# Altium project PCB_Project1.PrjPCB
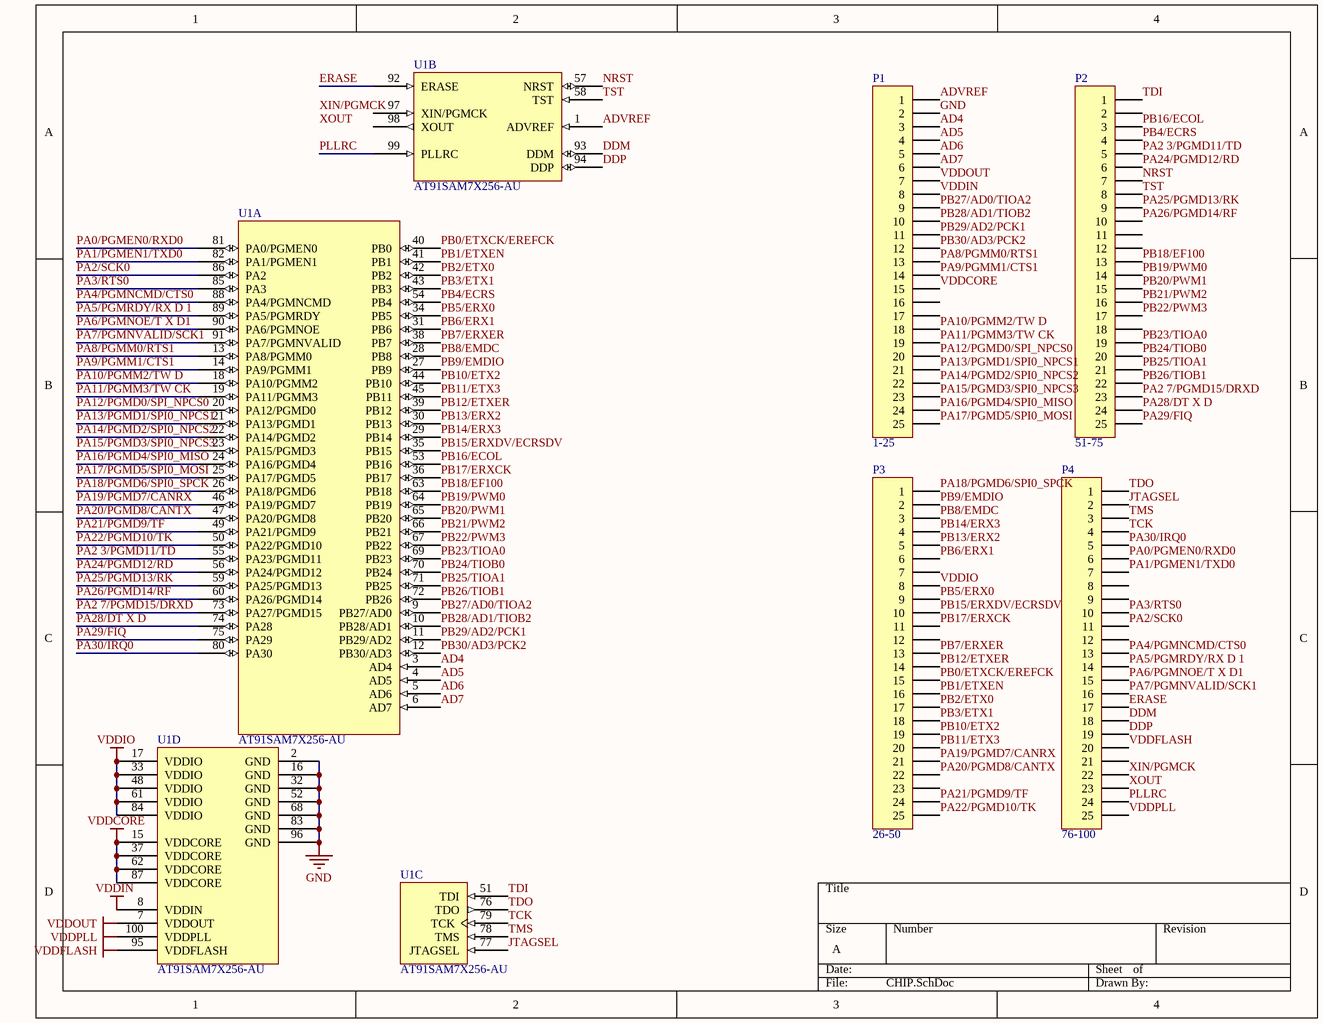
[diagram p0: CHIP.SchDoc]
1 sheet, 5 parts. Net scope: global (net labels, ports and power ports of the same name join across sheets).
Board file: PCB1.PcbDoc

## Sheet CHIP.SchDoc
size A

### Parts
P1  1-25  [HDR1X25]
P2  51-75  [HDR1X25]
P3  26-50  [HDR1X25]
P4  76-100  [HDR1X25]
U1  AT91SAM7X256-AU  [LQFP100_N]  (parts A,B,C,D of 4)

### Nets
GND: P1.2 U1.2(GND) U1.16(GND) U1.32(GND) U1.52(GND) U1.68(GND) U1.83(GND) U1.96(GND)
VDDCORE: P1.15 U1.15(VDDCORE) U1.37(VDDCORE) U1.62(VDDCORE) U1.87(VDDCORE)
VDDFLASH: P4.20 U1.95(VDDFLASH)  [also labelled VDDFLASH ]
VDDIN: P1.8 U1.8(VDDIN)  [also labelled VDDIN ]
VDDIO: P3.8 U1.17(VDDIO) U1.33(VDDIO) U1.48(VDDIO) U1.61(VDDIO) U1.84(VDDIO)
VDDOUT: P1.7 U1.7(VDDOUT)  [also labelled VDDOUT ]
VDDPLL: P4.25 U1.100(VDDPLL)  [also labelled VDDPLL ]
AD4: P1.3 U1.3(AD4)  [also labelled AD4 ]
AD5: P1.4 U1.4(AD5)  [also labelled AD5 ]
AD6: P1.5 U1.5(AD6)
AD7: P1.6 U1.6(AD7)
ADVREF: P1.1 U1.1(ADVREF)  [also labelled ADVREF ]
DDM: P4.18 U1.93(DDM)  [also labelled DDM ]
DDP: P4.19 U1.94(DDP)  [also labelled DDP ]
ERASE: P4.17 U1.92(ERASE)  [also labelled ERASE ]
JTAGSEL: P4.2 U1.77(JTAGSEL)  [also labelled JTAGSEL ]
NRST: P2.7 U1.57(NRST)  [also labelled NRST ]
PA0/PGMEN0/RXD0: P4.6 U1.81(PA0/PGMEN0)  [also labelled PA0/PGMEN0/RXD0 ]
PA1/PGMEN1/TXD0: P4.7 U1.82(PA1/PGMEN1)  [also labelled PA1/PGMEN1/TXD0 ]
PA2 3/PGMD11/TD: P2.5 U1.55(PA23/PGMD11)  [also labelled PA2 3/PGMD11/TD ]
PA2 7/PGMD15/DRXD: P2.23 U1.73(PA27/PGMD15)  [also labelled PA2 7/PGMD15/DRXD ]
PA2/SCK0: P4.11 U1.86(PA2)
PA3/RTS0: P4.10 U1.85(PA3)  [also labelled PA3/RTS0 ]
PA4/PGMNCMD/CTS0: P4.13 U1.88(PA4/PGMNCMD)  [also labelled PA4/PGMNCMD/CTS0 ]
PA5/PGMRDY/RX D 1: P4.14 U1.89(PA5/PGMRDY)  [also labelled PA5/PGMRDY/RX D 1 ]
PA6/PGMNOE/T X D1: P4.15 U1.90(PA6/PGMNOE)  [also labelled PA6/PGMNOE/T X D1 ]
PA7/PGMNVALID/SCK1: P4.16 U1.91(PA7/PGMNVALID)  [also labelled PA7/PGMNVALID/SCK1 ]
PA8/PGMM0/RTS1: P1.13 U1.13(PA8/PGMM0)  [also labelled PA8/PGMM0/RTS1 ]
PA9/PGMM1/CTS1: P1.14 U1.14(PA9/PGMM1)  [also labelled PA9/PGMM1/CTS1 ]
PA10/PGMM2/TW D: P1.18 U1.18(PA10/PGMM2)  [also labelled PA10/PGMM2/TW D ]
PA11/PGMM3/TW CK: P1.19 U1.19(PA11/PGMM3)  [also labelled PA11/PGMM3/TW CK ]
PA12/PGMD0/SPI_NPCS0: P1.20 U1.20(PA12/PGMD0)  [also labelled PA12/PGMD0/SPI_NPCS0 ]
PA13/PGMD1/SPI0_NPCS1: P1.21 U1.21(PA13/PGMD1)  [also labelled PA13/PGMD1/SPI0_NPCS1 ]
PA14/PGMD2/SPI0_NPCS2: P1.22 U1.22(PA14/PGMD2)  [also labelled PA14/PGMD2/SPI0_NPCS2 ]
PA15/PGMD3/SPI0_NPCS3: P1.23 U1.23(PA15/PGMD3)  [also labelled PA15/PGMD3/SPI0_NPCS3 ]
PA16/PGMD4/SPI0_MISO: P1.24 U1.24(PA16/PGMD4)  [also labelled PA16/PGMD4/SPI0_MISO ]
PA17/PGMD5/SPI0_MOSI: P1.25 U1.25(PA17/PGMD5)  [also labelled PA17/PGMD5/SPI0_MOSI ]
PA18/PGMD6/SPI0_SPCK: P3.1 U1.26(PA18/PGMD6)  [also labelled PA18/PGMD6/SPI0_SPCK ]
PA19/PGMD7/CANRX: P3.21 U1.46(PA19/PGMD7)  [also labelled PA19/PGMD7/CANRX ]
PA20/PGMD8/CANTX: P3.22 U1.47(PA20/PGMD8)  [also labelled PA20/PGMD8/CANTX ]
PA21/PGMD9/TF: P3.24 U1.49(PA21/PGMD9)  [also labelled PA21/PGMD9/TF ]
PA22/PGMD10/TK: P3.25 U1.50(PA22/PGMD10)  [also labelled PA22/PGMD10/TK ]
PA24/PGMD12/RD: P2.6 U1.56(PA24/PGMD12)  [also labelled PA24/PGMD12/RD ]
PA25/PGMD13/RK: P2.9 U1.59(PA25/PGMD13)  [also labelled PA25/PGMD13/RK ]
PA26/PGMD14/RF: P2.10 U1.60(PA26/PGMD14)  [also labelled PA26/PGMD14/RF ]
PA28/DT X D: P2.24 U1.74(PA28)  [also labelled PA28/DT X D ]
PA29/FIQ: P2.25 U1.75(PA29)  [also labelled PA29/FIQ ]
PA30/IRQ0: P4.5 U1.80(PA30)  [also labelled PA30/IRQ0 ]
PB0/ETXCK/EREFCK: P3.15 U1.40(PB0)  [also labelled PB0/ETXCK/EREFCK ]
PB1/ETXEN: P3.16 U1.41(PB1)  [also labelled PB1/ETXEN ]
PB2/ETX0: P3.17 U1.42(PB2)  [also labelled PB2/ETX0 ]
PB3/ETX1: P3.18 U1.43(PB3)  [also labelled PB3/ETX1 ]
PB4/ECRS: P2.4 U1.54(PB4)  [also labelled PB4/ECRS ]
PB5/ERX0: P3.9 U1.34(PB5)
PB6/ERX1: P3.6 U1.31(PB6)
PB7/ERXER: P3.13 U1.38(PB7)  [also labelled PB7/ERXER ]
PB8/EMDC: P3.3 U1.28(PB8)  [also labelled PB8/EMDC ]
PB9/EMDIO: P3.2 U1.27(PB9)  [also labelled PB9/EMDIO ]
PB10/ETX2: P3.19 U1.44(PB10)  [also labelled PB10/ETX2 ]
PB11/ETX3: P3.20 U1.45(PB11)  [also labelled PB11/ETX3 ]
PB12/ETXER: P3.14 U1.39(PB12)
PB13/ERX2: P3.5 U1.30(PB13)  [also labelled PB13/ERX2 ]
PB14/ERX3: P3.4 U1.29(PB14)  [also labelled PB14/ERX3 ]
PB15/ERXDV/ECRSDV : P3.10 U1.35(PB15)
PB16/ECOL: P2.3 U1.53(PB16)
PB17/ERXCK: P3.11 U1.36(PB17)  [also labelled PB17/ERXCK ]
PB18/EF100: P2.13 U1.63(PB18)  [also labelled PB18/EF100 ]
PB19/PWM0: P2.14 U1.64(PB19)  [also labelled PB19/PWM0 ]
PB20/PWM1: P2.15 U1.65(PB20)  [also labelled PB20/PWM1 ]
PB21/PWM2: P2.16 U1.66(PB21)  [also labelled PB21/PWM2 ]
PB22/PWM3: P2.17 U1.67(PB22)  [also labelled PB22/PWM3 ]
PB23/TIOA0: P2.19 U1.69(PB23)  [also labelled PB23/TIOA0 ]
PB24/TIOB0 : P2.20 U1.70(PB24)
PB25/TIOA1: P2.21 U1.71(PB25)  [also labelled PB25/TIOA1 ]
PB26/TIOB1: P2.22 U1.72(PB26)  [also labelled PB26/TIOB1 ]
PB27/AD0/TIOA2: P1.9 U1.9(PB27/AD0)
PB28/AD1/TIOB2: P1.10 U1.10(PB28/AD1)  [also labelled PB28/AD1/TIOB2 ]
PB29/AD2/PCK1: P1.11 U1.11(PB29/AD2)  [also labelled PB29/AD2/PCK1 ]
PB30/AD3/PCK2: P1.12 U1.12(PB30/AD3)  [also labelled PB30/AD3/PCK2 ]
PLLRC: P4.24 U1.99(PLLRC)  [also labelled PLLRC ]
TCK: P4.4 U1.79(TCK)  [also labelled TCK ]
TDI: P2.1 U1.51(TDI)  [also labelled TDI ]
TDO: P4.1 U1.76(TDO)  [also labelled TDO ]
TMS: P4.3 U1.78(TMS)  [also labelled TMS ]
TST: P2.8 U1.58(TST)  [also labelled TST ]
XIN/PGMCK: P4.22
XOUT: P4.23

Not connected (* = marked no-connect by the designer): P1 16 17; P2 2 11 12 18; P3 7 12 23; P4 8 9 12 21; U1 97(XIN/PGMCK) 98(XOUT)

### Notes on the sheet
- Labels drawn without touching a wire or pin: XIN/PGMCK , XOUT 

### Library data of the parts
P1-P4 = Header 25: Header, 25-Pin
U1 = AT91SAM7X256-AU: Smart ARM Microcontroller, ARM7TDMI 32-Bit RISC CPU, 256KB Flash and 64KB SRAM, 100-Pin LQFP, Industrial, Pb-Free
